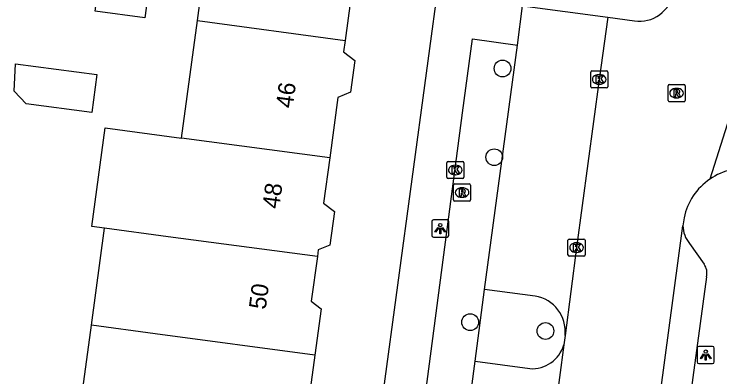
# Model space of a CAD drawing. Extents: x 161258 to 161838, y 380836 to 381727.
# Drawn here: x 161698.32 to 161739.61, y 381528.61 to 381549.82 of the extents above; entities that cross this region are included whole.
import ezdxf

# ---------------------------------------------------------------- set-up
doc = ezdxf.new("R2010")
doc.units = 0
for name, color, linetype in [('IMGEO_Boom', 7, 'Continuous'), ('IMGEO_Kolk', 7, 'Continuous'), ('IMGEO_Lichtpunt', 7, 'Continuous'), ('IMGEO_Pand', 7, 'Continuous'), ('IMGEO_Pand_nummerreeks', 7, 'Continuous'), ('IMGEO_Rijbaan_lokaal_open', 7, 'Continuous'), ('IMGEO_Rioolput', 7, 'Continuous'), ('IMGEO_Voetpad_open', 7, 'Continuous')]:
    doc.layers.add(name, color=color, linetype=linetype)

msp = doc.modelspace()

# ---------------------------------------------------------------- linework, layer by layer
at = {"layer": 'IMGEO_Boom'}
for centre in [(161726.893, 381546.639), (161726.409, 381541.449), (161725, 381531.806), (161729.402, 381531.29)]:
    msp.add_circle(centre, 0.489, dxfattribs=at)
at = {"layer": 'IMGEO_Kolk'}
for p, q in [((161732.05, 381545.574), (161732.05, 381546.426)), ((161732.125, 381546.5), (161732.977, 381546.5)), ((161733.051, 381546.426), (161733.051, 381545.574)), ((161732.538, 381546.28), (161732.563, 381546.28)), ((161732.561, 381545.72), (161732.536, 381545.72)), ((161732.977, 381545.5), (161732.125, 381545.5)), ((161723.629, 381540.279), (161723.629, 381541.131)), ((161723.704, 381541.205), (161724.556, 381541.205)), ((161724.63, 381541.131), (161724.63, 381540.279)), ((161724.117, 381540.985), (161724.142, 381540.985)), ((161724.556, 381540.205), (161723.704, 381540.205)), ((161724.14, 381540.425), (161724.115, 381540.425)), ((161730.721, 381535.74), (161730.721, 381536.592)), ((161730.796, 381536.666), (161731.648, 381536.666)), ((161731.209, 381536.446), (161731.234, 381536.446)), ((161731.722, 381536.592), (161731.722, 381535.74)), ((161731.648, 381535.666), (161730.796, 381535.666)), ((161731.232, 381535.886), (161731.207, 381535.886))]:
    msp.add_line(p, q, dxfattribs=at)
for points in [[(161732.05, 381545.574), (161732.05, 381546.426)], [(161732.125, 381546.5), (161732.977, 381546.5)], [(161733.051, 381546.426), (161733.051, 381545.574)], [(161732.371, 381546.2), (161732.494, 381546.2), (161732.494, 381546.049), (161732.624, 381546.2), (161732.788, 381546.2), (161732.642, 381546.049), (161732.795, 381545.8), (161732.643, 381545.8), (161732.558, 381545.964), (161732.494, 381545.897), (161732.494, 381545.8), (161732.371, 381545.8), (161732.371, 381546.2)], [(161732.977, 381545.5), (161732.125, 381545.5)], [(161723.629, 381540.279), (161723.629, 381541.131)], [(161723.704, 381541.205), (161724.556, 381541.205)], [(161724.63, 381541.131), (161724.63, 381540.279)], [(161723.95, 381540.905), (161724.073, 381540.905), (161724.073, 381540.754), (161724.203, 381540.905), (161724.367, 381540.905), (161724.221, 381540.754), (161724.374, 381540.505), (161724.222, 381540.505), (161724.137, 381540.669), (161724.073, 381540.602), (161724.073, 381540.505), (161723.95, 381540.505), (161723.95, 381540.905)], [(161724.556, 381540.205), (161723.704, 381540.205)], [(161730.721, 381535.74), (161730.721, 381536.592)], [(161730.796, 381536.666), (161731.648, 381536.666)], [(161731.722, 381536.592), (161731.722, 381535.74)], [(161731.042, 381536.366), (161731.165, 381536.366), (161731.165, 381536.215), (161731.295, 381536.366), (161731.459, 381536.366), (161731.313, 381536.215), (161731.466, 381535.966), (161731.314, 381535.966), (161731.229, 381536.13), (161731.165, 381536.063), (161731.165, 381535.966), (161731.042, 381535.966), (161731.042, 381536.366)], [(161731.648, 381535.666), (161730.796, 381535.666)]]:
    msp.add_lwpolyline(points, dxfattribs=at)
for centre, start, end in [((161732.127, 381546.424), 91.552, 178.448), ((161732.127, 381546.424), 91.552, 178.448), ((161732.975, 381546.424), 1.552, 88.448), ((161732.975, 381546.424), 1.552, 88.448), ((161732.127, 381545.576), 181.552, 268.448), ((161732.127, 381545.576), 181.552, 268.448), ((161732.975, 381545.576), 271.552, 358.448), ((161732.975, 381545.576), 271.552, 358.448), ((161723.706, 381541.129), 91.552, 178.448), ((161723.706, 381541.129), 91.552, 178.448), ((161724.554, 381541.129), 1.552, 88.448), ((161724.554, 381541.129), 1.552, 88.448), ((161723.706, 381540.281), 181.552, 268.448), ((161723.706, 381540.281), 181.552, 268.448), ((161724.554, 381540.281), 271.552, 358.448), ((161724.554, 381540.281), 271.552, 358.448), ((161730.798, 381536.59), 91.552, 178.448), ((161730.798, 381536.59), 91.552, 178.448), ((161731.646, 381536.59), 1.552, 88.448), ((161731.646, 381536.59), 1.552, 88.448), ((161730.798, 381535.742), 181.552, 268.448), ((161730.798, 381535.742), 181.552, 268.448), ((161731.646, 381535.742), 271.552, 358.448), ((161731.646, 381535.742), 271.552, 358.448)]:
    msp.add_arc(centre, 0.0765, start, end, dxfattribs=at)
for centre, major_axis, ratio, start_param, end_param in [((161732.537, 381546), (-0.387, 0.002), 0.722429, 4.712389, 7.853982), ((161732.562, 381546), (-0.39, 0.002), 0.717154, 1.570796, 4.712389), ((161724.116, 381540.705), (-0.387, 0.002), 0.722429, 4.712389, 7.853982), ((161724.141, 381540.705), (-0.39, 0.002), 0.717154, 1.570796, 4.712389), ((161731.208, 381536.166), (-0.387, 0.002), 0.722429, 4.712389, 7.853982), ((161731.233, 381536.166), (-0.39, 0.002), 0.717154, 1.570796, 4.712389)]:
    msp.add_ellipse(centre, major_axis=major_axis, ratio=ratio, start_param=start_param, end_param=end_param, dxfattribs=at)
at = {"layer": 'IMGEO_Lichtpunt'}
for p, q in [((161722.752, 381537.686), (161722.752, 381536.879)), ((161722.752, 381537.686), (161722.752, 381536.879)), ((161723.654, 381537.781), (161722.846, 381537.781)), ((161723.654, 381537.781), (161722.846, 381537.781)), ((161723.748, 381536.879), (161723.748, 381537.686)), ((161723.748, 381536.879), (161723.748, 381537.686)), ((161722.846, 381536.785), (161723.654, 381536.785)), ((161722.846, 381536.785), (161723.654, 381536.785)), ((161738.278, 381530.29), (161738.278, 381529.483)), ((161738.278, 381530.29), (161738.278, 381529.483)), ((161739.18, 381530.385), (161738.372, 381530.385)), ((161739.18, 381530.385), (161738.372, 381530.385)), ((161739.274, 381529.483), (161739.274, 381530.29)), ((161739.274, 381529.483), (161739.274, 381530.29)), ((161738.372, 381529.389), (161739.18, 381529.389)), ((161738.372, 381529.389), (161739.18, 381529.389))]:
    msp.add_line(p, q, dxfattribs=at)
for points in [[(161723.126, 381537.35), (161723.165, 381537.322), (161722.977, 381537.06), (161722.939, 381537.087), (161723.126, 381537.35)], [(161723.228, 381537.302), (161723.275, 381537.302), (161723.275, 381536.98), (161723.228, 381536.98), (161723.228, 381537.302)], [(161723.338, 381537.322), (161723.376, 381537.349), (161723.563, 381537.087), (161723.524, 381537.059), (161723.338, 381537.322)], [(161738.652, 381529.954), (161738.691, 381529.926), (161738.503, 381529.664), (161738.465, 381529.691), (161738.652, 381529.954)], [(161738.754, 381529.906), (161738.801, 381529.906), (161738.801, 381529.584), (161738.754, 381529.584), (161738.754, 381529.906)], [(161738.864, 381529.926), (161738.902, 381529.953), (161739.089, 381529.691), (161739.05, 381529.663), (161738.864, 381529.926)]]:
    msp.add_lwpolyline(points, dxfattribs=at)
for centre in [(161723.251, 381537.484), (161738.777, 381530.088)]:
    msp.add_circle(centre, 0.0994, dxfattribs=at)
for centre, start, end in [((161722.846, 381537.686), 90, 180), ((161722.846, 381537.686), 90, 180), ((161723.654, 381537.686), 0, 90), ((161723.654, 381537.686), 0, 90), ((161722.846, 381536.879), 180, 270), ((161722.846, 381536.879), 180, 270), ((161723.654, 381536.879), 270, 0), ((161723.654, 381536.879), 270, 360), ((161738.372, 381530.29), 90, 180), ((161738.372, 381530.29), 90, 180), ((161739.18, 381530.29), 0, 90), ((161739.18, 381530.29), 0, 90), ((161738.372, 381529.483), 180, 270), ((161738.372, 381529.483), 180, 270), ((161739.18, 381529.483), 270, 0), ((161739.18, 381529.483), 270, 360)]:
    msp.add_arc(centre, 0.0946, start, end, dxfattribs=at)
at = {"layer": 'IMGEO_Pand'}
for points in [[(161709.045, 381549.435), (161709.773, 381554.819)], [(161719.133, 381553.564), (161718.775, 381550.918), (161718.003, 381550.602), (161717.689, 381548.283)], [(161703.07, 381549.987), (161703.344, 381552.016), (161706.247, 381551.591), (161705.978, 381549.6), (161703.07, 381549.987)], [(161708.115, 381542.559), (161709.045, 381549.435)], [(161709.045, 381549.435), (161717.689, 381548.283)], [(161717.689, 381548.283), (161717.599, 381547.618), (161718.253, 381547.113), (161718.001, 381545.253), (161717.265, 381544.951), (161716.786, 381541.408)], [(161698.397, 381546.912), (161703.167, 381546.283), (161702.874, 381544.06), (161699.024, 381544.567), (161698.323, 381545.322), (161698.397, 381546.912)], [(161703.611, 381537.308), (161702.878, 381537.407), (161703.656, 381543.162), (161708.115, 381542.559)], [(161716.786, 381541.408), (161708.115, 381542.559)], [(161716.786, 381541.408), (161716.428, 381538.763), (161717.059, 381538.276), (161716.793, 381536.31), (161716.114, 381536.031), (161716.062, 381535.646)], [(161702.843, 381531.624), (161703.611, 381537.308)], [(161716.062, 381535.646), (161707.337, 381536.804), (161703.611, 381537.308)], [(161716.062, 381535.646), (161715.708, 381533.032), (161716.284, 381532.588), (161715.917, 381529.873)], [(161704.472, 381525.437), (161702.05, 381525.76), (161702.843, 381531.624)], [(161715.917, 381529.873), (161706.569, 381531.125), (161702.843, 381531.624)], [(161715.917, 381529.873), (161715.529, 381527.004), (161714.809, 381526.709), (161714.457, 381524.101)]]:
    msp.add_lwpolyline(points, dxfattribs=at)
at = {"layer": 'IMGEO_Rijbaan_lokaal_open'}
for points in [[(161733.053, 381549.631), (161732.552, 381545.999), (161731.224, 381536.166), (161730.548, 381531.036)], [(161733.053, 381549.631), (161734.603, 381549.425)], [(161741.055, 381546.559), (161739.018, 381540.168)], [(161737.511, 381537.91), (161737.448, 381537.445)], [(161735.58, 381523.626), (161737.448, 381537.445)], [(161730.548, 381531.036), (161730.473, 381530.472)], [(161730.473, 381530.472), (161729.966, 381526.66), (161728.672, 381516.798), (161728.292, 381514.383)]]:
    msp.add_lwpolyline(points, dxfattribs=at)
for centre, radius, start, end in [((161734.918, 381551.373), 1.973, 260.8004, 351.5604), ((161741.066, 381537.17), 3.631, 80.4351, 124.3294), ((161741.071, 381537.166), 3.637, 124.3663, 168.195)]:
    msp.add_arc(centre, radius, start, end, dxfattribs=at)
at = {"layer": 'IMGEO_Rioolput'}
for p, q in [((161736.574, 381544.772), (161736.574, 381545.624)), ((161736.649, 381545.698), (161737.501, 381545.698)), ((161737.575, 381545.624), (161737.575, 381544.772)), ((161737.062, 381545.478), (161737.087, 381545.478)), ((161737.085, 381544.918), (161737.06, 381544.918)), ((161737.501, 381544.698), (161736.649, 381544.698)), ((161724.023, 381538.959), (161724.023, 381539.811)), ((161724.098, 381539.885), (161724.95, 381539.885)), ((161725.024, 381539.811), (161725.024, 381538.959)), ((161724.511, 381539.665), (161724.536, 381539.665)), ((161724.534, 381539.105), (161724.509, 381539.105)), ((161724.95, 381538.885), (161724.098, 381538.885))]:
    msp.add_line(p, q, dxfattribs=at)
for points in [[(161736.574, 381544.772), (161736.574, 381545.624)], [(161736.649, 381545.698), (161737.501, 381545.698)], [(161737.575, 381545.624), (161737.575, 381544.772)], [(161737.163, 381545.396), (161736.911, 381545.398), (161736.911, 381544.998)], [(161736.911, 381544.998), (161737.035, 381544.998), (161737.035, 381545.16), (161737.046, 381545.16)], [(161737.089, 381545.317), (161737.035, 381545.317), (161737.035, 381545.236)], [(161737.035, 381545.236), (161737.087, 381545.236)], [(161737.093, 381545.131), (161737.164, 381544.998), (161737.304, 381544.998), (161737.239, 381545.124)], [(161737.501, 381544.698), (161736.649, 381544.698)], [(161724.023, 381538.959), (161724.023, 381539.811)], [(161724.098, 381539.885), (161724.95, 381539.885)], [(161725.024, 381539.811), (161725.024, 381538.959)], [(161724.612, 381539.583), (161724.36, 381539.585), (161724.36, 381539.185)], [(161724.36, 381539.185), (161724.484, 381539.185), (161724.484, 381539.347), (161724.495, 381539.347)], [(161724.538, 381539.504), (161724.484, 381539.504), (161724.484, 381539.423)], [(161724.484, 381539.423), (161724.536, 381539.423)], [(161724.542, 381539.318), (161724.613, 381539.185), (161724.753, 381539.185), (161724.688, 381539.311)], [(161724.95, 381538.885), (161724.098, 381538.885)]]:
    msp.add_lwpolyline(points, dxfattribs=at)
for centre, radius, start, end in [((161736.651, 381545.622), 0.0765, 91.552, 178.448), ((161736.651, 381545.622), 0.0765, 91.552, 178.448), ((161737.499, 381545.622), 0.0765, 1.552, 88.448), ((161737.499, 381545.622), 0.0765, 1.552, 88.448), ((161737.045, 381545.107), 0.0533, 26.0293, 88.6989), ((161737.071, 381545.425), 0.19, 274.7715, 282.9687), ((161737.095, 381545.221), 0.0964, 77.0061, 93.1865), ((161737.109, 381545.278), 0.0378, 276.6634, 79.6772), ((161737.162, 381545.286), 0.109, 350.3612, 89.416), ((161737.16, 381545.286), 0.112, 277.5842, 350.9817), ((161737.144, 381545.071), 0.108, 29.5134, 73.7905), ((161736.651, 381544.774), 0.0765, 181.552, 268.448), ((161736.651, 381544.774), 0.0765, 181.552, 268.448), ((161737.499, 381544.774), 0.0765, 271.552, 358.448), ((161737.499, 381544.774), 0.0765, 271.552, 358.448), ((161724.1, 381539.809), 0.0765, 91.552, 178.448), ((161724.1, 381539.809), 0.0765, 91.552, 178.448), ((161724.948, 381539.809), 0.0765, 1.552, 88.448), ((161724.948, 381539.809), 0.0765, 1.552, 88.448), ((161724.494, 381539.294), 0.0533, 26.0293, 88.6989), ((161724.52, 381539.612), 0.19, 274.7715, 282.9687), ((161724.544, 381539.408), 0.0964, 77.0061, 93.1865), ((161724.558, 381539.465), 0.0378, 276.6634, 79.6772), ((161724.611, 381539.473), 0.109, 350.3612, 89.416), ((161724.609, 381539.473), 0.112, 277.5842, 350.9817), ((161724.593, 381539.258), 0.108, 29.5134, 73.7905), ((161724.1, 381538.961), 0.0765, 181.552, 268.448), ((161724.1, 381538.961), 0.0765, 181.552, 268.448), ((161724.948, 381538.961), 0.0765, 271.552, 358.448), ((161724.948, 381538.961), 0.0765, 271.552, 358.448)]:
    msp.add_arc(centre, radius, start, end, dxfattribs=at)
for centre, major_axis, ratio, start_param, end_param in [((161737.061, 381545.198), (-0.387, 0.002), 0.722429, 4.712389, 7.853982), ((161737.086, 381545.198), (-0.39, 0.002), 0.717154, 1.570796, 4.712389), ((161724.51, 381539.385), (-0.387, 0.002), 0.722429, 4.712389, 7.853982), ((161724.535, 381539.385), (-0.39, 0.002), 0.717154, 1.570796, 4.712389)]:
    msp.add_ellipse(centre, major_axis=major_axis, ratio=ratio, start_param=start_param, end_param=end_param, dxfattribs=at)
at = {"layer": 'IMGEO_Voetpad_open'}
for points in [[(161717.412, 381509.172), (161725.791, 381571.18)], [(161727.76, 381548.004), (161728.067, 381550.294), (161733.053, 381549.631)], [(161723.447, 381515.547), (161720.85, 381515.886), (161720.838, 381515.888), (161724.557, 381544.042), (161725.131, 381548.374), (161727.76, 381548.004)], [(161725.842, 381533.715), (161727.76, 381548.004)], [(161737.833, 381536.402), (161738.682, 381535.202)], [(161738.828, 381534.45), (161737.653, 381525.849)], [(161725.287, 381529.523), (161725.842, 381533.715)], [(161728.799, 381533.322), (161725.842, 381533.715)], [(161723.447, 381515.547), (161725.287, 381529.523)], [(161725.287, 381529.523), (161728.489, 381529.09)]]:
    msp.add_lwpolyline(points, dxfattribs=at)
for centre, radius, start, end in [((161739.082, 381537.456), 1.634, 180.3764, 220.1446), ((161737.912, 381534.662), 0.94, 346.9387, 35.0357), ((161728.474, 381531.262), 2.086, 353.7918, 81.0468), ((161728.624, 381531.011), 1.926, 265.9824, 343.7376)]:
    msp.add_arc(centre, radius, start, end, dxfattribs=at)

# ---------------------------------------------------------------- texts
at = {"layer": 'IMGEO_Pand_nummerreeks'}
for s, rotation, p in [('46', 82.3602, (161714.616, 381544.283)), ('48', 82.3627, (161713.828, 381538.4)), ('50', 82.3627, (161713.038, 381532.514))]:
    msp.add_text(s, height=1, rotation=rotation, dxfattribs=at).set_placement(p)

doc.saveas('drawing.dxf')
